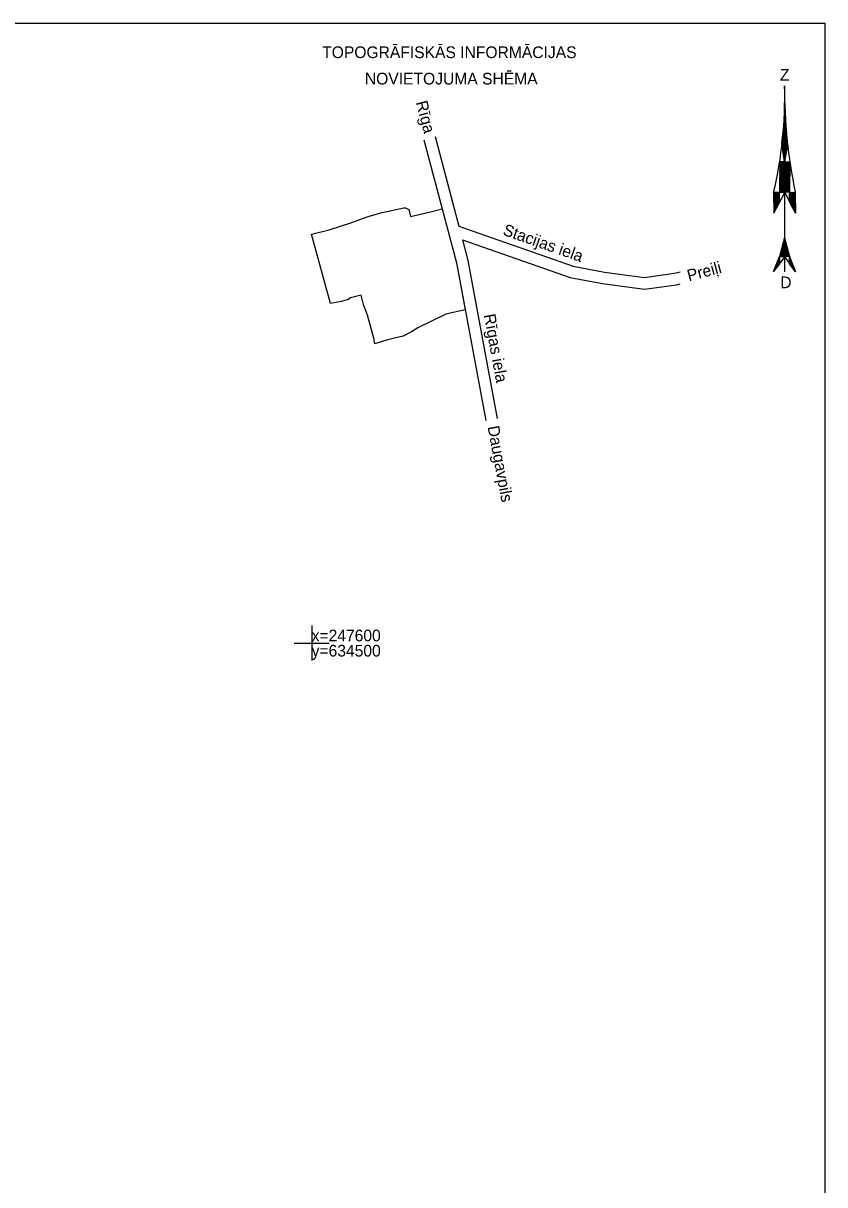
# Model space of a CAD drawing. Extents: x 634272 to 634544, y 247463 to 247653.
# Drawn here: x 634475.3 to 634543.9, y 247553.7 to 247653 of the extents above; entities that cross this region are included whole.
import ezdxf

# ---------------------------------------------------------------- set-up
doc = ezdxf.new("R2010")
doc.units = 0
for name, color, linetype in [('GEOD_ELEM_####_####_#', 7, 'Continuous'), ('GEOD_KORD_####_TKST_#', 7, 'Continuous'), ('RAMI_PLAN_####_TKST_#', 7, 'Continuous')]:
    doc.layers.add(name, color=color, linetype=linetype)

msp = doc.modelspace()

# ---------------------------------------------------------------- linework, layer by layer
at = {"layer": 'GEOD_ELEM_####_####_#'}
for p, q in [((634500, 247601.5), (634500, 247600)), ((634498.5, 247600), (634500, 247600)), ((634500, 247600), (634500, 247598.5)), ((634500, 247600), (634501.5, 247600))]:
    msp.add_line(p, q, dxfattribs=at)
at = {"layer": 'RAMI_PLAN_####_TKST_#'}
for p, q in [((634540.472, 247647.65), (634540.472, 247631.74)), ((634540.379, 247643.956), (634540.613, 247643.722)), ((634540.386, 247644.019), (634540.604, 247643.801)), ((634540.393, 247644.083), (634540.596, 247643.88)), ((634540.4, 247644.147), (634540.588, 247643.959)), ((634540.407, 247644.21), (634540.58, 247644.038)), ((634540.414, 247644.274), (634540.572, 247644.117)), ((634540.421, 247644.338), (634540.564, 247644.196)), ((634540.428, 247644.402), (634540.555, 247644.274)), ((634540.435, 247644.465), (634540.547, 247644.353)), ((634540.442, 247644.529), (634540.539, 247644.432)), ((634540.449, 247644.593), (634540.531, 247644.511)), ((634540.456, 247644.656), (634540.523, 247644.59)), ((634540.463, 247644.72), (634540.515, 247644.669)), ((634540.47, 247644.784), (634540.506, 247644.748)), ((634540.477, 247644.848), (634540.498, 247644.827)), ((634540.484, 247644.911), (634540.49, 247644.905)), ((634540.275, 247643), (634540.717, 247642.558)), ((634540.282, 247643.063), (634540.727, 247642.618)), ((634540.289, 247643.127), (634540.719, 247642.697)), ((634540.295, 247643.191), (634540.711, 247642.776)), ((634540.302, 247643.255), (634540.702, 247642.855)), ((634540.309, 247643.318), (634540.694, 247642.934)), ((634540.316, 247643.382), (634540.686, 247643.012)), ((634540.323, 247643.446), (634540.678, 247643.091)), ((634540.33, 247643.51), (634540.67, 247643.17)), ((634540.337, 247643.573), (634540.662, 247643.249)), ((634540.344, 247643.637), (634540.653, 247643.328)), ((634540.351, 247643.701), (634540.645, 247643.407)), ((634540.358, 247643.764), (634540.637, 247643.486)), ((634540.365, 247643.828), (634540.629, 247643.565)), ((634540.372, 247643.892), (634540.621, 247643.643)), ((634540.248, 247642.744), (634540.674, 247642.317)), ((634540.254, 247642.809), (634540.685, 247642.377)), ((634540.259, 247642.662), (634540.663, 247642.257)), ((634540.261, 247642.872), (634540.695, 247642.438)), ((634540.268, 247642.936), (634540.706, 247642.498)), ((634540.271, 247642.579), (634540.653, 247642.197)), ((634540.282, 247642.497), (634540.642, 247642.137)), ((634540.294, 247642.415), (634540.632, 247642.077)), ((634540.305, 247642.333), (634540.621, 247642.017)), ((634540.316, 247642.251), (634540.61, 247641.957)), ((634540.328, 247642.169), (634540.6, 247641.897)), ((634540.339, 247642.086), (634540.589, 247641.837)), ((634540.351, 247642.004), (634540.579, 247641.776)), ((634540.051, 247640.628), (634540.47, 247641.047)), ((634540.051, 247640.557), (634540.47, 247640.976)), ((634540.052, 247640.771), (634540.437, 247641.156)), ((634540.052, 247640.7), (634540.469, 247641.117)), ((634540.053, 247640.913), (634540.296, 247641.156)), ((634540.053, 247640.842), (634540.367, 247641.156)), ((634540.054, 247641.056), (634540.155, 247641.156)), ((634540.054, 247640.984), (634540.225, 247641.156)), ((634540.055, 247641.127), (634540.084, 247641.156)), ((634540.362, 247641.922), (634540.568, 247641.716)), ((634540.374, 247641.84), (634540.557, 247641.656)), ((634540.385, 247641.758), (634540.547, 247641.596)), ((634540.397, 247641.676), (634540.536, 247641.536)), ((634540.408, 247641.593), (634540.526, 247641.476)), ((634540.419, 247641.511), (634540.515, 247641.416)), ((634540.431, 247641.429), (634540.504, 247641.356)), ((634540.442, 247641.347), (634540.494, 247641.296)), ((634540.454, 247641.265), (634540.483, 247641.236)), ((634540.465, 247641.183), (634540.472, 247641.175)), ((634540.469, 247641.132), (634540.922, 247640.679)), ((634540.47, 247641.061), (634540.921, 247640.609)), ((634540.47, 247640.99), (634540.921, 247640.539)), ((634540.516, 247641.156), (634540.922, 247640.749)), ((634540.587, 247641.156), (634540.923, 247640.82)), ((634540.657, 247641.156), (634540.923, 247640.89)), ((634540.728, 247641.156), (634540.924, 247640.96)), ((634540.799, 247641.156), (634540.924, 247641.03)), ((634540.869, 247641.156), (634540.925, 247641.101)), ((634540.044, 247639.632), (634540.474, 247640.061)), ((634540.044, 247639.56), (634540.474, 247639.991)), ((634540.045, 247639.774), (634540.473, 247640.202)), ((634540.045, 247639.703), (634540.474, 247640.132)), ((634540.046, 247639.916), (634540.473, 247640.343)), ((634540.046, 247639.845), (634540.473, 247640.272)), ((634540.047, 247640.059), (634540.472, 247640.484)), ((634540.047, 247639.988), (634540.472, 247640.413)), ((634540.048, 247640.201), (634540.471, 247640.624)), ((634540.048, 247640.13), (634540.472, 247640.554)), ((634540.049, 247640.344), (634540.471, 247640.765)), ((634540.049, 247640.272), (634540.471, 247640.695)), ((634540.05, 247640.486), (634540.47, 247640.906)), ((634540.05, 247640.415), (634540.47, 247640.835)), ((634540.47, 247640.919), (634540.921, 247640.468)), ((634540.471, 247640.847), (634540.92, 247640.398)), ((634540.471, 247640.776), (634540.92, 247640.328)), ((634540.472, 247640.705), (634540.919, 247640.258)), ((634540.472, 247640.634), (634540.919, 247640.187)), ((634540.473, 247640.563), (634540.918, 247640.117)), ((634540.473, 247640.492), (634540.918, 247640.047)), ((634540.474, 247640.42), (634540.917, 247639.977)), ((634540.474, 247640.349), (634540.917, 247639.906)), ((634540.474, 247640.278), (634540.916, 247639.836)), ((634540.475, 247640.207), (634540.916, 247639.766)), ((634540.475, 247640.136), (634540.915, 247639.696)), ((634540.476, 247640.065), (634540.915, 247639.625)), ((634540.476, 247639.994), (634540.915, 247639.555)), ((634540.037, 247638.564), (634540.479, 247639.005)), ((634540.038, 247638.706), (634540.478, 247639.146)), ((634540.038, 247638.635), (634540.479, 247639.076)), ((634540.039, 247638.92), (634540.477, 247639.357)), ((634540.039, 247638.848), (634540.478, 247639.287)), ((634540.039, 247638.777), (634540.478, 247639.217)), ((634540.04, 247639.062), (634540.477, 247639.498)), ((634540.04, 247638.991), (634540.477, 247639.428)), ((634540.041, 247639.204), (634540.476, 247639.639)), ((634540.041, 247639.133), (634540.476, 247639.569)), ((634540.042, 247639.347), (634540.475, 247639.78)), ((634540.042, 247639.276), (634540.476, 247639.709)), ((634540.043, 247639.489), (634540.475, 247639.92)), ((634540.043, 247639.418), (634540.475, 247639.85)), ((634540.477, 247639.922), (634540.914, 247639.485)), ((634540.477, 247639.851), (634540.914, 247639.415)), ((634540.477, 247639.78), (634540.913, 247639.344)), ((634540.478, 247639.709), (634540.913, 247639.274)), ((634540.478, 247639.638), (634540.912, 247639.204)), ((634540.479, 247639.567), (634540.912, 247639.134)), ((634540.479, 247639.496), (634540.911, 247639.063)), ((634540.48, 247639.424), (634540.911, 247638.993)), ((634540.48, 247639.353), (634540.91, 247638.923)), ((634540.48, 247639.282), (634540.91, 247638.853)), ((634540.481, 247639.211), (634540.909, 247638.782)), ((634540.481, 247639.14), (634540.909, 247638.712)), ((634540.482, 247639.069), (634540.909, 247638.642)), ((634540.482, 247638.998), (634540.908, 247638.572)), ((634539.53, 247638.507), (634539.543, 247638.52)), ((634539.53, 247638.519), (634539.555, 247636.757)), ((634539.531, 247638.438), (634539.62, 247638.526)), ((634539.532, 247638.368), (634539.696, 247638.532)), ((634539.533, 247638.298), (634539.773, 247638.538)), ((634539.534, 247638.228), (634539.85, 247638.544)), ((634539.535, 247638.159), (634539.927, 247638.55)), ((634539.536, 247638.089), (634540.003, 247638.556)), ((634539.537, 247638.019), (634540.037, 247638.519)), ((634539.538, 247637.95), (634540.037, 247638.448)), ((634539.539, 247637.88), (634540.037, 247638.378)), ((634539.54, 247637.81), (634540.037, 247638.307)), ((634539.541, 247637.74), (634540.037, 247638.236)), ((634539.542, 247637.671), (634540.037, 247638.166)), ((634539.543, 247637.601), (634540.037, 247638.095)), ((634539.544, 247637.531), (634540.037, 247638.024)), ((634539.555, 247636.757), (634540.485, 247638.544)), ((634540.103, 247638.558), (634540.479, 247638.935)), ((634540.173, 247638.558), (634540.48, 247638.865)), ((634540.243, 247638.557), (634540.48, 247638.794)), ((634540.313, 247638.557), (634540.48, 247638.724)), ((634540.383, 247638.556), (634540.481, 247638.653)), ((634540.453, 247638.555), (634540.481, 247638.583)), ((634540.483, 247638.926), (634540.857, 247638.552)), ((634540.483, 247638.855), (634540.788, 247638.55)), ((634540.484, 247638.784), (634540.719, 247638.549)), ((634540.484, 247638.713), (634540.649, 247638.547)), ((634540.484, 247638.642), (634540.58, 247638.546)), ((634540.485, 247638.571), (634540.511, 247638.545)), ((634540.485, 247638.544), (634541.415, 247636.757)), ((634540.904, 247638.046), (634541.404, 247637.547)), ((634540.904, 247637.976), (634541.405, 247637.475)), ((634540.905, 247638.187), (634541.402, 247637.69)), ((634540.905, 247638.116), (634541.403, 247637.618)), ((634540.906, 247638.327), (634541.4, 247637.833)), ((634540.906, 247638.257), (634541.401, 247637.762)), ((634540.907, 247638.467), (634541.398, 247637.977)), ((634540.907, 247638.397), (634541.399, 247637.905)), ((634540.908, 247638.538), (634541.397, 247638.049)), ((634540.964, 247638.552), (634541.396, 247638.12)), ((634541.036, 247638.551), (634541.395, 247638.192)), ((634541.108, 247638.549), (634541.394, 247638.264)), ((634541.18, 247638.548), (634541.393, 247638.335)), ((634541.253, 247638.547), (634541.392, 247638.407)), ((634541.325, 247638.545), (634541.391, 247638.479)), ((634541.415, 247636.757), (634541.39, 247638.544)), ((634539.545, 247637.461), (634540.037, 247637.953)), ((634539.546, 247637.392), (634540.037, 247637.883)), ((634539.547, 247637.322), (634540.037, 247637.812)), ((634539.548, 247637.252), (634540.037, 247637.741)), ((634539.549, 247637.183), (634540.018, 247637.652)), ((634539.55, 247637.113), (634539.942, 247637.505)), ((634539.551, 247637.043), (634539.867, 247637.359)), ((634539.552, 247636.973), (634539.791, 247637.212)), ((634539.553, 247636.904), (634539.715, 247637.066)), ((634540.902, 247637.766), (634541.408, 247637.26)), ((634540.903, 247637.906), (634541.406, 247637.403)), ((634540.903, 247637.836), (634541.407, 247637.331)), ((634540.947, 247637.65), (634541.409, 247637.188)), ((634541.025, 247637.501), (634541.41, 247637.116)), ((634541.103, 247637.353), (634541.411, 247637.045)), ((634541.181, 247637.204), (634541.412, 247636.973)), ((634541.258, 247637.056), (634541.413, 247636.901)), ((634539.554, 247636.834), (634539.639, 247636.919)), ((634539.555, 247636.764), (634539.563, 247636.772)), ((634541.336, 247636.907), (634541.414, 247636.829)), ((634541.414, 247636.759), (634541.415, 247636.758)), ((634540.241, 247633.808), (634540.482, 247634.048)), ((634540.267, 247633.904), (634540.481, 247634.117)), ((634540.293, 247634.001), (634540.479, 247634.187)), ((634540.319, 247634.098), (634540.478, 247634.257)), ((634540.345, 247634.194), (634540.477, 247634.326)), ((634540.372, 247634.291), (634540.476, 247634.396)), ((634540.398, 247634.388), (634540.475, 247634.465)), ((634540.424, 247634.485), (634540.474, 247634.535)), ((634540.45, 247634.581), (634540.473, 247634.605)), ((634540.478, 247634.612), (634540.491, 247634.6)), ((634540.479, 247634.541), (634540.517, 247634.503)), ((634540.48, 247634.469), (634540.543, 247634.407)), ((634540.481, 247634.398), (634540.569, 247634.31)), ((634540.482, 247634.326), (634540.595, 247634.213)), ((634540.483, 247634.254), (634540.621, 247634.117)), ((634540.484, 247634.183), (634540.647, 247634.02)), ((634540.484, 247634.111), (634540.673, 247633.923)), ((634540.485, 247634.04), (634540.699, 247633.826)), ((634540.047, 247633.047), (634540.49, 247633.491)), ((634540.059, 247633.131), (634540.489, 247633.56)), ((634540.085, 247633.227), (634540.488, 247633.63)), ((634540.111, 247633.324), (634540.487, 247633.7)), ((634540.119, 247633.048), (634540.491, 247633.421)), ((634540.137, 247633.421), (634540.486, 247633.769)), ((634540.163, 247633.517), (634540.485, 247633.839)), ((634540.189, 247633.614), (634540.484, 247633.908)), ((634540.191, 247633.05), (634540.492, 247633.351)), ((634540.215, 247633.711), (634540.483, 247633.978)), ((634540.263, 247633.051), (634540.493, 247633.282)), ((634540.335, 247633.052), (634540.495, 247633.212)), ((634540.407, 247633.053), (634540.496, 247633.143)), ((634540.478, 247633.055), (634540.497, 247633.073)), ((634540.486, 247633.968), (634540.725, 247633.73)), ((634540.487, 247633.897), (634540.75, 247633.633)), ((634540.488, 247633.825), (634540.776, 247633.536)), ((634540.489, 247633.753), (634540.802, 247633.44)), ((634540.49, 247633.682), (634540.828, 247633.343)), ((634540.49, 247633.61), (634540.854, 247633.246)), ((634540.491, 247633.539), (634540.88, 247633.15)), ((634540.492, 247633.467), (634540.906, 247633.053)), ((634540.493, 247633.396), (634540.84, 247633.048)), ((634540.494, 247633.324), (634540.768, 247633.05)), ((634540.495, 247633.253), (634540.696, 247633.051)), ((634540.495, 247633.181), (634540.624, 247633.053)), ((634540.496, 247633.109), (634540.552, 247633.054)), ((634540.908, 247633.027), (634540.92, 247633.015)), ((634539.535, 247631.77), (634540.501, 247633.006)), ((634539.585, 247631.898), (634539.801, 247632.114)), ((634539.631, 247632.014), (634540.037, 247632.42)), ((634539.677, 247632.131), (634540.037, 247632.491)), ((634539.723, 247632.247), (634540.037, 247632.562)), ((634539.768, 247632.364), (634540.037, 247632.632)), ((634539.814, 247632.48), (634540.037, 247632.703)), ((634539.86, 247632.597), (634540.037, 247632.774)), ((634539.906, 247632.713), (634540.037, 247632.844)), ((634539.952, 247632.83), (634540.037, 247632.915)), ((634539.997, 247632.946), (634540.037, 247632.986)), ((634540.501, 247633.006), (634541.397, 247631.74)), ((634540.908, 247632.957), (634540.962, 247632.902)), ((634540.908, 247632.886), (634541.004, 247632.79)), ((634540.908, 247632.815), (634541.047, 247632.677)), ((634540.908, 247632.744), (634541.089, 247632.564)), ((634540.908, 247632.674), (634541.131, 247632.451)), ((634540.908, 247632.603), (634541.173, 247632.338)), ((634540.908, 247632.532), (634541.216, 247632.225)), ((634540.908, 247632.462), (634541.258, 247632.112)), ((634540.997, 247632.302), (634541.3, 247631.999)), ((634541.172, 247632.056), (634541.343, 247631.886)), ((634539.539, 247631.781), (634539.558, 247631.8)), ((634541.347, 247631.811), (634541.385, 247631.773))]:
    msp.add_line(p, q, dxfattribs=at)
for points in [[(634272.074, 247653.005), (634543.915, 247653.005), (634543.915, 247462.947), (634272.074, 247462.947)], [(634540.469, 247641.156), (634540.247, 247642.749), (634540.487, 247644.936), (634540.727, 247642.617)], [(634540.055, 247641.156), (634540.037, 247638.559), (634540.481, 247638.555), (634540.469, 247641.156)], [(634540.469, 247641.156), (634540.925, 247641.156), (634540.908, 247638.553), (634540.485, 247638.544)], [(634539.53, 247638.519), (634539.555, 247636.757), (634540.037, 247637.688), (634540.037, 247638.559)], [(634541.415, 247636.757), (634540.902, 247637.736), (634540.908, 247638.553), (634541.39, 247638.544)], [(634499.999, 247634.969), (634501.5, 247635.35), (634503.364, 247635.923), (634504.136, 247636.219), (634504.908, 247636.516), (634506.025, 247636.827), (634507.899, 247637.206), (634508.034, 247637.226), (634508.304, 247637.086), (634508.455, 247636.465), (634510.042, 247636.86), (634511.164, 247637.137), (634512.395, 247632.508), (634513.139, 247628.502), (634511.483, 247628.129), (634509.1, 247626.954), (634508.541, 247626.606), (634507.82, 247626.259), (634506.496, 247625.937), (634505.416, 247625.592), (634505.322, 247626.061), (634504.781, 247628.05), (634504.431, 247628.944), (634504.246, 247629.757), (634503.33, 247629.515), (634503.119, 247629.37), (634502.543, 247629.207), (634501.606, 247629.035)], [(634540.037, 247633.047), (634540.497, 247633.055), (634540.472, 247634.665)], [(634540.478, 247634.647), (634540.908, 247633.047), (634540.497, 247633.055)], [(634540.037, 247633.047), (634540.037, 247632.418), (634539.535, 247631.77)], [(634540.908, 247633.047), (634541.397, 247631.74), (634540.908, 247632.427)]]:
    msp.add_lwpolyline(points, close=True, dxfattribs=at)
for points in [[(634509.592, 247643.048), (634512.395, 247632.508), (634514.896, 247619.036)], [(634510.558, 247643.305), (634512.592, 247635.658)], [(634512.592, 247635.658), (634522.373, 247632.23), (634525.05, 247631.724), (634528.486, 247631.269), (634531.012, 247631.623), (634531.524, 247631.76)], [(634512.903, 247634.489), (634522.113, 247631.261), (634524.892, 247630.737), (634528.489, 247630.26), (634531.211, 247630.641), (634531.524, 247630.725)], [(634512.903, 247634.489), (634513.372, 247632.728), (634515.879, 247619.218)]]:
    msp.add_lwpolyline(points, dxfattribs=at)
for centre, radius, start, end in [((634505.481, 247646.648), 35.007, 346.57619, 1.64364), ((634581.967, 247647.236), 41.496, 179.42537, 192.08801), ((634528.349, 247637.032), 12.362, 334.81857, 348.88604), ((634554.522, 247637.49), 14.327, 191.43572, 203.65126)]:
    msp.add_arc(centre, radius, start, end, dxfattribs=at)

# ---------------------------------------------------------------- texts
at = {"layer": 'GEOD_KORD_####_TKST_#'}
for s, p in [('x=247600', (634500, 247600.15)), ('y=634500', (634500, 247598.85))]:
    msp.add_text(s, height=1, dxfattribs=at).set_placement(p)
at = {"layer": 'RAMI_PLAN_####_TKST_#'}
for s, p in [('TOPOGRĀFISKĀS INFORMĀCIJAS', (634500.901, 247650.024)), ('NOVIETOJUMA SHĒMA', (634504.554, 247647.766)), ('Z', (634540.071, 247648.088)), ('D', (634540.101, 247630.348))]:
    msp.add_text(s, height=1, dxfattribs=at).set_placement(p)
for s, rotation, p in [('Rīga', 284.89636, (634508.905, 247646.238)), ('Stacijas iela', 340.68373, (634516.291, 247634.93)), ('Preiļi', 14.98628, (634532.285, 247630.92)), ('Rīgas iela', 280.51548, (634514.72, 247628.059)), ('Daugavpils', 280.51548, (634515.051, 247618.495))]:
    msp.add_text(s, height=1, rotation=rotation, dxfattribs=at).set_placement(p)

doc.saveas('drawing.dxf')
